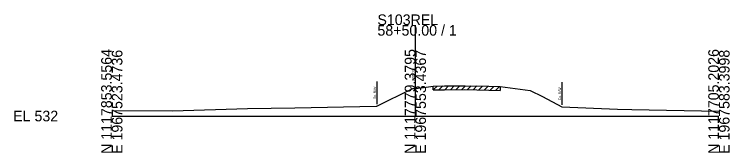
# Model space of a CAD drawing. Extents: x -26 to 163, y -10 to 24518.
# Drawn here: x -25.7 to 162.8, y 8990.3 to 9026.9 of the extents above; entities that cross this region are included whole.
import ezdxf

# ---------------------------------------------------------------- set-up
doc = ezdxf.new("R2010")
doc.units = 0
for name, color, linetype in [('RD_GPK_XS_Cell', 7, 'Continuous'), ('RD_XS_ExGround', 7, 'Continuous'), ('RD_XS_ExPaveRet', 7, 'Continuous'), ('RD_XS_ExRW', 7, 'Continuous'), ('RD_XS_TX_Elev_EX', 7, 'Continuous')]:
    doc.layers.add(name, color=color, linetype=linetype)

msp = doc.modelspace()

# ---------------------------------------------------------------- linework, layer by layer
at = {"layer": 'RD_GPK_XS_Cell'}
for p, q in [((80, 9000), (80, 9024.03)), ((0, 9000), (80, 9000)), ((80, 9000), (160, 9000))]:
    msp.add_line(p, q, dxfattribs=at)
at = {"layer": 'RD_XS_ExGround'}
msp.add_lwpolyline([(0, 9001.47), (15.98, 9001.37), (35.74, 9001.97), (48.26, 9002.2), (69.63, 9002.59), (69.89, 9002.63), (72.87, 9004.09), (79.35, 9007.23), (80, 9007.31), (82.84, 9007.66), (84.73, 9007.89), (87.71, 9007.93), (93.07, 9008.01), (99.37, 9007.85), (102.34, 9007.77), (104.98, 9007.43), (110.29, 9006.72), (113.54, 9005.12), (118.62, 9002.42), (133.25, 9001.85), (137.05, 9001.7), (160, 9001.3)], dxfattribs=at)
at = {"layer": 'RD_XS_ExPaveRet'}
for p, q in [((84.73, 9006.89), (85.75, 9007.91)), ((84.73, 9006.89), (84.73, 9007.89)), ((84.73, 9006.89), (87.71, 9006.93)), ((86.23, 9006.91), (87.25, 9007.93)), ((87.71, 9006.93), (93.07, 9007.01)), ((87.73, 9006.93), (88.75, 9007.95)), ((89.23, 9006.95), (90.25, 9007.97)), ((90.73, 9006.98), (91.75, 9007.99)), ((92.23, 9007), (93.24, 9008.01)), ((93.07, 9007.01), (99.37, 9006.85)), ((93.73, 9006.99), (94.71, 9007.97)), ((95.23, 9006.96), (96.21, 9007.93)), ((96.73, 9006.92), (97.71, 9007.89)), ((98.23, 9006.88), (99.21, 9007.86)), ((99.37, 9006.85), (102.34, 9006.77)), ((99.73, 9006.84), (100.71, 9007.82)), ((101.23, 9006.8), (102.21, 9007.78)), ((102.34, 9007.77), (102.34, 9006.77))]:
    msp.add_line(p, q, dxfattribs=at)
at = {"layer": 'RD_XS_ExRW'}
for p, q in [((69.89, 9009.13), (69.89, 9003.13)), ((118.62, 9008.92), (118.62, 9002.92))]:
    msp.add_line(p, q, dxfattribs=at)

# ---------------------------------------------------------------- texts
at = {"layer": 'RD_GPK_XS_Cell'}
for s, p in [('S103REL', (70, 9024.03)), ('58+50.00 / 1', (70, 9021.23)), ('EL 532', (-26, 8998.6))]:
    msp.add_text(s, height=2.8, dxfattribs=at).set_placement(p)
for s, p in [('N 1117853.5564', (0, 8990)), ('N 1117779.3795', (80, 8990)), ('N 1117705.2026', (160, 8990)), ('E 1967523.4736', (2.8, 8990)), ('E 1967553.4367', (82.8, 8990)), ('E 1967583.3998', (162.8, 8990))]:
    msp.add_text(s, height=2.8, rotation=90, dxfattribs=at).set_placement(p)
at = {"layer": 'RD_XS_ExRW'}
for p in [(69.64, 9004.47), (118.37, 9004.26)]:
    msp.add_text('Ex. R/W ', height=0.65, rotation=90, dxfattribs=at).set_placement(p)
at = {"layer": 'RD_XS_TX_Elev_EX'}
msp.add_text('539.31', height=0.8, rotation=90, dxfattribs=at).set_placement((79.9, 9009.31))

doc.saveas('drawing.dxf')
